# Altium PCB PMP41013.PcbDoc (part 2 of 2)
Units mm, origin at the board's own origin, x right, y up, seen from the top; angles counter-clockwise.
Board outline 51.82 x 50.04 mm, 2 copper layers (Top Layer, Bottom Layer), stack 0.325 mm thick; 134 components, 74 nets, 429 pads, 1513 vias.
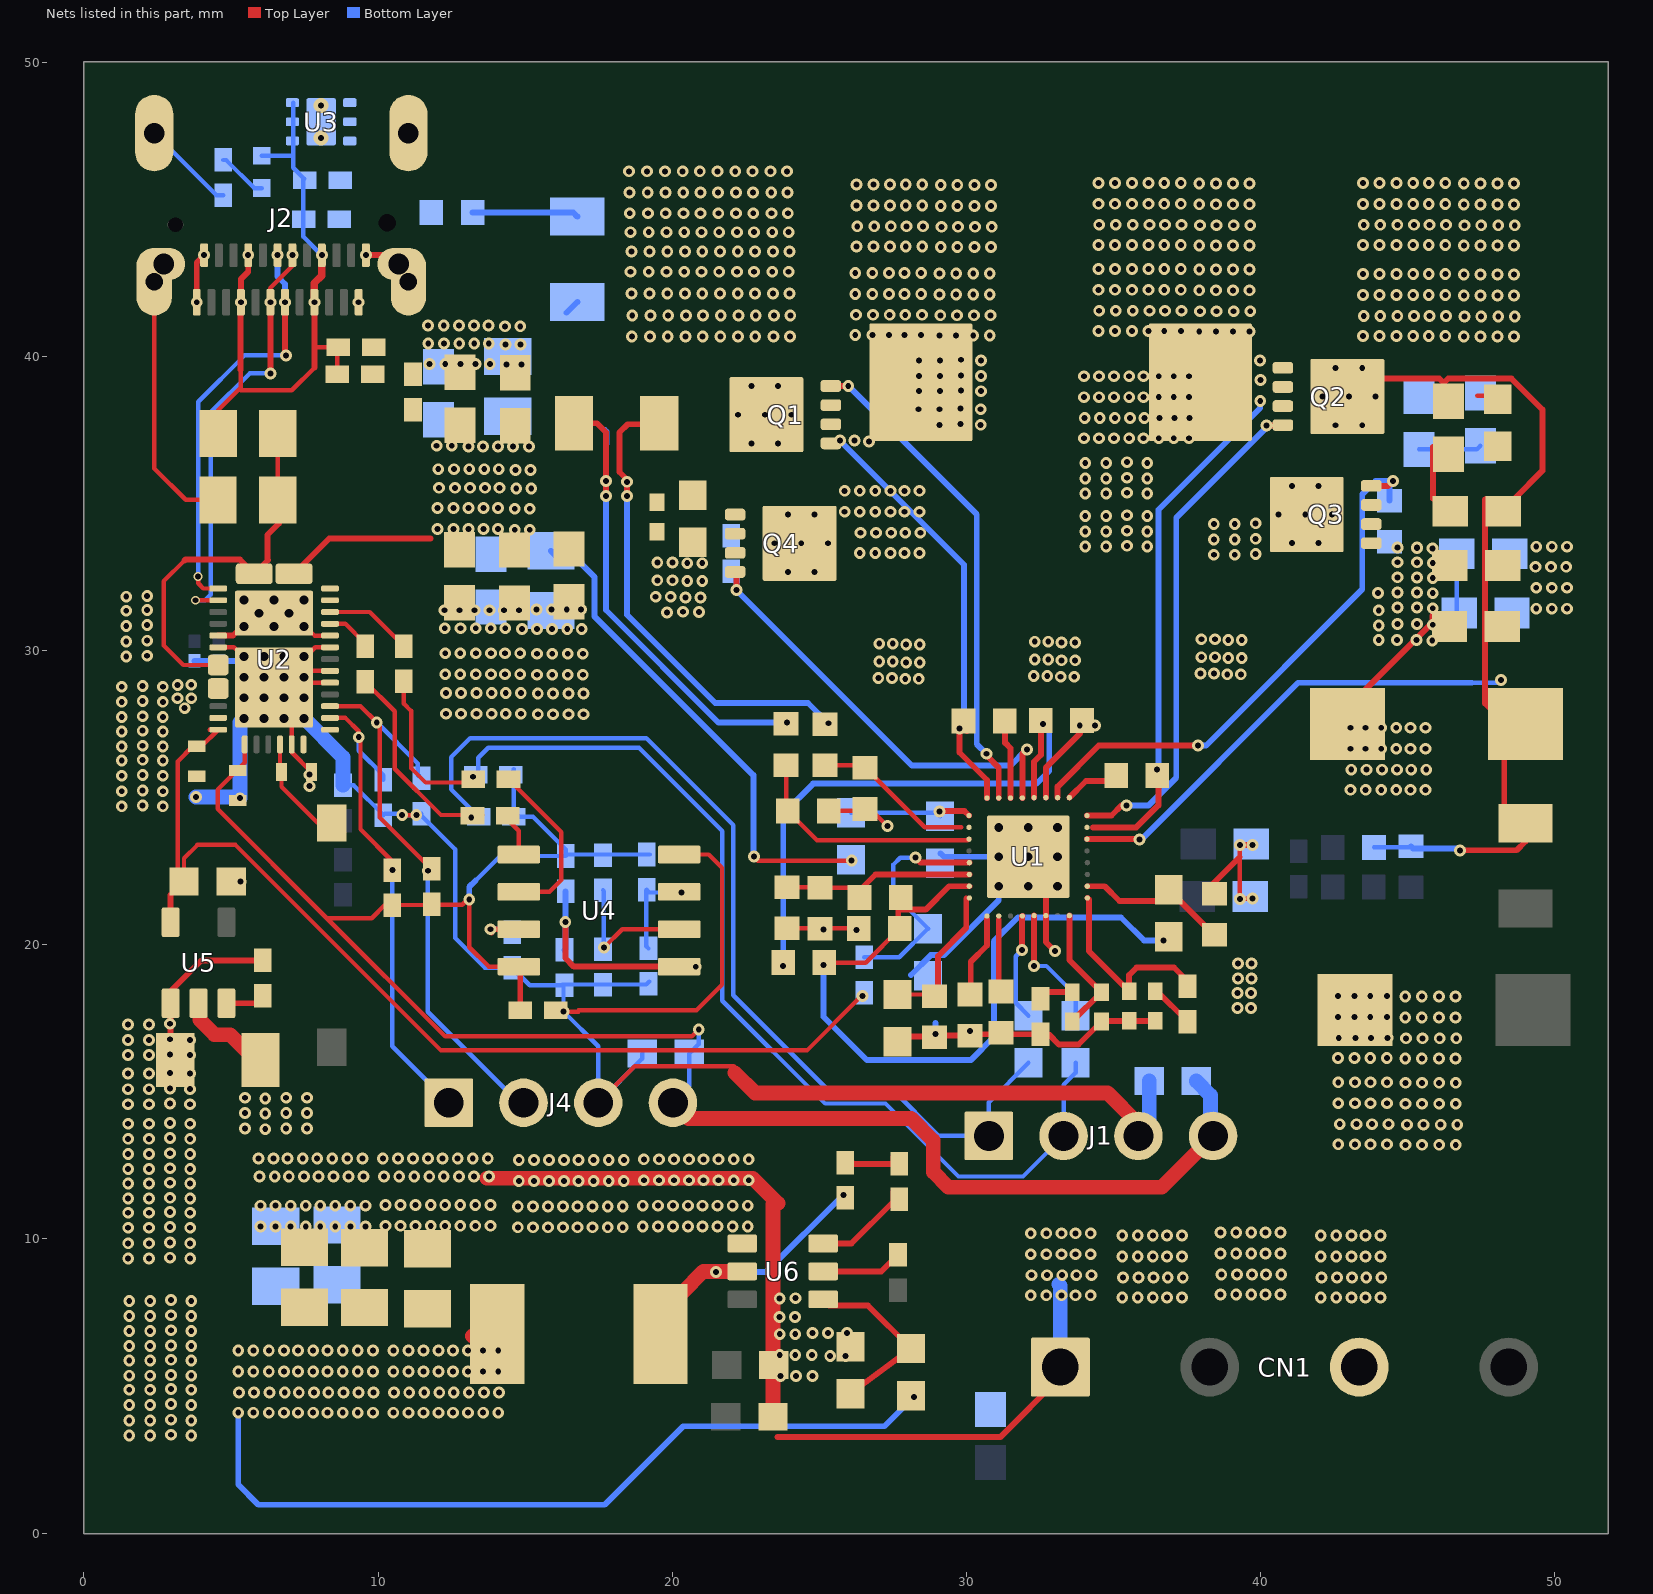
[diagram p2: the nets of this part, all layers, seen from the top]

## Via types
v1: diameter 0.4, hole 0.2, Top Layer to Bottom Layer, 1333 vias
v2: diameter 0.406, hole 0.203, Top Layer to Bottom Layer, tented both sides, 81 vias
v3: diameter 0.6, hole 0.3, Top Layer to Bottom Layer, 33 vias
v4: diameter 0.4, hole 0.2, Top Layer to Bottom Layer, tented both sides, 31 vias
v5: diameter 0.5, hole 0.2, Top Layer to Bottom Layer, 26 vias
v6: diameter 0.3, hole 0.2, Top Layer to Bottom Layer, tented both sides, 5 vias
v7: diameter 0.5, hole 0.2, Top Layer to Bottom Layer, tented both sides, 4 vias

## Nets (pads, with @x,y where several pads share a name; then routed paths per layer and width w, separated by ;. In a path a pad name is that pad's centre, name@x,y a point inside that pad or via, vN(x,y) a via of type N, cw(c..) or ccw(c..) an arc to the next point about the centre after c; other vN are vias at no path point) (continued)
GND: C1.2 C2.2 C3.2 C4.2 C5.2 C6.2 C7.2 C8.2 C9.2 C10.2 C11.2 C12.2 C13.2 C14.2 C15.2 C16.2 C17.2 C18.2 C19.2 C20.2 C21.2 C24.2 C25.1 C26.1 C27.2 C28.1 C29.2 C30.2 C33.2 C34.2 C35.1 C36.2 C37.2 C38.2 C39.2 C40.2 C41.2 C42.2 C43.1 C44.2 C45.2 C46.2 C47.2 C48.2 C49.1 C50.1 C51.2 C52.2 C53.2 C54.2 C55.2 C56.2 C57.2 C58.1 C59.2 C60.2 C61.2 C62.2 C64.2 C65.2 C66.2 C67.2 C68.2 CN1.1 J1.3 J2.A1 J2.A12 J2.B1 J2.B12 J2.S1 J2.S2 J2.S3 J2.S4 J4.3 Q3.1 Q3.2 Q3.3 Q4.1 Q4.2 Q4.3 R4.1 R16.2 R19.1 R20.1 R21.1 R22.2 R24.1 R32.1 R33.1 R42.1 R43.1 R44.1 R45.1 R50.1 U1.14 U1.27 U1.33 U2.5 U2.11 U2.12 U2.14 U2.31 U2.39 U3.1 U3.2 U3.3 U3.7@8.065,47.974 U4.4 U5.2 U6.1 | length 173.5
  Top Layer w0.15: J2.S2@2.394,42.54 2.394,36.189 3.461,35.122 C51.2@4.559,35.122 ; v4(3.816,25.019) 3.816,25.053 v4@3.839,25.075 ; U2.31@4.568,30.109 5.103,30.109 U2.39@6.468,28.744 ; C49.1@5.337,25.044 C49.1@5.349,25.057 ; U2.39@6.468,27.709 U2.39@6.468,28.744 ; U2.39@6.808,28.909 U2.39@6.664,28.909 ; U2.39@7.488,28.909 U2.11@8.368,28.909 ; C50.1@7.735,25.875 7.068,26.543 U2.5@7.068,26.809 7.068,28.144 U2.39@6.468,28.744 ; U2.12@8.368,29.309 U2.39@7.064,29.309 ; U2.14@8.368,30.109 7.864,30.109 U2.39@7.064,29.309 ; v4(10.82,24.409) v4(11.303,24.409) ; C57.2@16.035,17.776 16.082,17.729 v4(16.307,17.729) 16.815,17.729 ; 16.815,17.776 20.825,17.776 21.692,18.643 21.692,22.62 21.244,23.067 U4.4@20.237,23.067 ; J4.3@17.485,14.629 18.732,15.875 22.098,15.875 22.229,15.744 ; C40.2@23.911,20.557 26.328,20.557 C33.2@26.336,20.549 ; C29.2@25.327,24.549 26.494,24.549 C28.1@26.56,24.615 26.736,24.615 v2(27.311,24.04) ; v2(39.294,23.393) 39.294,22.981 v2(39.294,21.552) 39.306,21.565 v2(39.726,21.565) ; U2.39@6.468,28.744 U2.39@6.633,28.909 ; U2.39@6.633,28.909 7.033,29.309 U2.39@7.064,29.309 ; U2.39@6.633,28.909 U2.39@6.664,28.909 ; U2.39@6.664,28.909 U2.39@7.064,29.309
  Top Layer w0.2: v2(3.839,41.84) 3.839,43.19 v2(4.089,43.44) ; 3.937,17.45 U5.2@3.937,17.655 ; U5.2@3.994,17.918 U5.2@4.09,18.013 ; v2(9.589,43.44) 10.134,43.44 J2.S1@11.034,42.54 11.35,42.224 11.35,42.499 J2.S1@10.709,43.14 J2.S1@11.101,43.532 ; 23.581,3.264 31.15,3.264 33.194,5.308 CN1.1@33.194,5.643 ; R20.1@27.518,16.886 C42.2@28.645,16.886 ; C42.2@29.039,16.916 29.964,16.916 30.006,16.959 C37.2@32.522,16.959 32.796,16.959 33.145,16.61 33.814,16.61 C35.1@34.593,17.389 34.619,17.414 C39.2@35.533,17.414 C38.2@36.422,17.414 ; v3(32.101,22.99) 32.701,22.39 U1.14@32.701,20.99 32.701,20.094 v2(33.009,19.787) ; U1.27@32.701,25.001 32.701,26.021 33.856,27.176 C36.2@33.856,27.379 ; R21.1@38.584,21.806 38.352,22.039 39.294,22.981 ; v2(39.294,23.393) v2(39.726,23.393) ; C1.2@42.338,27.449 45.834,30.946 C13.2@45.834,31.197 ; C14.2@45.86,35.16 45.86,36.927
  Top Layer w0.5: U5.2@3.899,18.013 3.899,17.693 U5.2@3.937,17.655 ; 3.937,17.45 4.445,16.942 4.978,16.942 5.839,16.081 C59.2@6.007,16.081 ; v1@13.698,12.066 22.74,12.066 23.593,11.213 23.573,11.193 ; 22.131,15.645 22.816,14.961 34.798,14.961 35.845,13.914 J1.3@35.845,13.502 ; C61.2@23.427,3.956 23.427,11.181
  Bottom Layer w0.15: J2.S4@2.394,47.59 4.508,45.476 R4.1@4.738,45.476 ; 8.788,26.394 8.788,25.446 R24.1@8.812,25.423 9.17,25.423 R32.1@10.183,24.409 10.226,24.452 v4@10.82,24.452 ; v4(10.82,24.409) v4(11.303,24.409) 11.456,24.409 12.624,23.241 12.624,20.229 13.635,19.218 R42.1@14.56,19.218 15.156,18.622 16.231,18.622 16.257,18.648 R44.1@17.647,18.648 19.122,18.648 R45.1@19.223,18.75 ; R33.1@11.245,24.452 R33.1@11.48,24.452 ; R43.1@16.307,18.592 v4(16.307,17.729) 17.485,16.551 J4.3@17.485,14.629 18.986,16.13 C43.1@18.986,16.307 ; 36.212,14.376 36.212,14.453 ; C15.2@45.386,36.836 47.35,36.836 C12.2@47.471,36.957 ; C16.2@46.673,33.24 46.673,31.271 C19.2@46.698,31.246
  Bottom Layer w0.2: C52.2@3.762,29.651 5.304,29.651 v3(5.448,29.794) ; J2.S3@11.034,47.554 J2.S3@11.034,47.59 ; 28.115,18.972 28.789,19.646 29.236,19.646 31.101,21.51 v3(31.101,21.99) ; v2(28.956,16.967) 28.956,17.344 ; C27.2@29.127,23.1 29.236,22.99 v3(31.101,22.99)
  Bottom Layer w0.5: v4(3.816,25.019) 5.272,25.019 v4(5.309,24.983) 5.309,27.555 v3(5.448,27.694) ; v3(7.488,27.694) 8.788,26.394 8.812,26.37 R24.1@8.812,25.423 ; 33.136,8.463 33.194,8.405 CN1.1@33.194,5.643 ; J1.3@35.845,13.502 36.212,13.869 36.212,14.376 ; 36.212,14.453 C58.1@36.212,15.37
  other v1: 23.681,5.34 24.209,5.34 24.768,5.34 25.369,6.02 25.897,6.02 23.655,6.051 24.184,6.051 24.747,6.051 23.655,6.762 24.184,6.762 24.77,6.799 25.298,6.799 23.645,7.347 24.174,7.347 23.652,7.977 24.196,7.987 35.297,8.007 35.826,8.007 36.339,8.007 36.819,8.007 37.332,8.007 42.045,8.007 42.573,8.007 43.086,8.007 43.567,8.007 44.079,8.007 32.19,8.083 32.718,8.083 33.231,8.083 33.711,8.083 34.224,8.083 38.641,8.109 39.17,8.109 39.683,8.109 40.163,8.109 40.676,8.109 35.323,8.693 35.851,8.693 36.364,8.693 36.844,8.693 37.357,8.693 42.07,8.693 42.599,8.693 43.112,8.693 43.592,8.693 44.105,8.693 32.215,8.769 32.744,8.769 33.256,8.769 33.737,8.769 34.25,8.769 38.667,8.794 39.195,8.794 39.708,8.794 40.188,8.794 40.701,8.794 35.297,9.404 35.826,9.404 36.339,9.404 36.819,9.404 37.332,9.404 42.045,9.404 42.573,9.404 43.086,9.404 43.567,9.404 44.079,9.404 32.19,9.48 32.718,9.48 33.231,9.48 33.711,9.48 34.224,9.48 38.641,9.506 39.17,9.506 39.683,9.506 40.163,9.506 40.676,9.506 35.297,10.115 35.826,10.115 36.339,10.115 36.819,10.115 37.332,10.115 42.045,10.115 42.573,10.115 43.086,10.115 43.567,10.115 44.079,10.115 32.19,10.191 32.718,10.191 33.231,10.191 33.711,10.191 34.224,10.191 38.641,10.217 39.17,10.217 39.683,10.217 40.163,10.217 40.676,10.217 14.753,10.395 15.266,10.395 15.779,10.395 16.291,10.395 16.782,10.395 17.295,10.395 17.808,10.395 18.321,10.395 6.006,10.42 6.518,10.42 7.031,10.42 7.544,10.42 8.035,10.42 8.548,10.42 9.06,10.42 9.573,10.42 19.001,10.42 19.514,10.42 20.027,10.42 20.539,10.42 21.031,10.42 21.543,10.42 22.056,10.42 22.569,10.42 10.254,10.445 10.766,10.445 11.279,10.445 11.792,10.445 12.283,10.445 12.796,10.445 13.309,10.445 13.821,10.445 14.753,11.106 15.266,11.106 15.779,11.106 16.291,11.106 16.782,11.106 17.295,11.106 17.808,11.106 18.321,11.106 6.006,11.131 6.518,11.131 7.031,11.131 7.544,11.131 8.035,11.131 8.548,11.131 9.06,11.131 9.573,11.131 19.001,11.131 19.514,11.131 20.027,11.131 20.539,11.131 21.031,11.131 21.543,11.131 22.056,11.131 22.569,11.131 10.254,11.157 10.766,11.157 11.279,11.157 11.792,11.157 12.283,11.157 12.796,11.157 13.309,11.157 13.821,11.157 14.788,11.969 15.301,11.969 15.813,11.969 16.326,11.969 16.817,11.969 17.33,11.969 17.843,11.969 18.356,11.969 19.036,11.995 19.549,11.995 20.061,11.995 20.574,11.995 21.065,11.995 21.578,11.995 22.091,11.995 22.604,11.995 5.976,12.122 6.489,12.122 6.969,12.122 7.482,12.122 7.973,12.122 8.486,12.122 8.999,12.122 9.512,12.122 10.207,12.122 10.72,12.122 11.232,12.122 11.745,12.122 12.236,12.122 12.749,12.122 13.262,12.122 13.774,12.122 14.788,12.681 15.301,12.681 15.813,12.681 16.326,12.681 16.817,12.681 17.33,12.681 17.843,12.681 18.356,12.681 19.036,12.706 19.549,12.706 20.061,12.706 20.574,12.706 21.065,12.706 21.578,12.706 22.091,12.706 22.604,12.706 5.935,12.731 6.447,12.731 6.928,12.731 7.441,12.731 7.932,12.731 8.444,12.731 8.957,12.731 9.47,12.731 10.165,12.731 10.678,12.731 11.191,12.731 11.703,12.731 12.194,12.731 12.707,12.731 13.22,12.731 13.733,12.731 42.642,13.215 43.205,13.215 43.737,13.215 44.3,13.215 44.928,13.198 45.491,13.198 46.071,13.198 46.634,13.198 6.168,13.732 5.482,13.757 6.879,13.757 7.59,13.757 42.693,13.901 43.256,13.901 43.787,13.901 44.351,13.901 44.979,13.884 45.542,13.884 46.122,13.884 46.685,13.884 6.168,14.26 5.482,14.286 6.879,14.286 7.59,14.286 42.642,14.612 43.205,14.612 43.737,14.612 44.3,14.612 44.928,14.595 45.491,14.595 46.071,14.595 46.634,14.595 6.168,14.773 5.482,14.798 6.879,14.798 7.59,14.798 42.642,15.323 43.205,15.323 43.737,15.323 44.3,15.323 44.928,15.306 45.491,15.306 46.071,15.306 46.634,15.306 44.919,16.134 45.482,16.134 46.062,16.134 46.625,16.134 42.633,16.151 43.196,16.151 43.727,16.151 44.291,16.151 44.944,16.819 45.508,16.819 46.087,16.819 46.651,16.819 42.658,16.837 43.222,16.837 43.753,16.837 44.316,16.837 44.919,17.531 45.482,17.531 46.062,17.531 46.625,17.531 42.633,17.548 43.196,17.548 43.727,17.548 44.291,17.548 44.919,18.242 45.482,18.242 46.062,18.242 46.625,18.242 42.633,18.259 43.196,18.259 43.727,18.259 44.291,18.259 43.059,25.266 43.572,25.266 44.1,25.266 44.613,25.266 45.093,25.266 45.606,25.266 43.084,25.952 43.597,25.952 44.126,25.952 44.638,25.952 45.119,25.952 45.632,25.952 43.059,26.663 43.572,26.663 44.1,26.663 44.613,26.663 45.093,26.663 45.606,26.663 43.059,27.374 43.572,27.374 44.1,27.374 44.613,27.374 45.093,27.374 45.606,27.374 33.853,27.45 34.376,27.45 12.308,27.85 12.821,27.85 13.35,27.85 13.863,27.85 14.343,27.85 14.856,27.85 15.433,27.833 15.945,27.833 16.474,27.833 16.987,27.833 12.308,28.562 12.821,28.562 13.35,28.562 13.863,28.562 14.343,28.562 14.856,28.562 15.433,28.545 15.945,28.545 16.474,28.545 16.987,28.545 27.922,29.04 28.382,29.04 27.007,29.065 27.467,29.065 33.205,29.108 33.665,29.108 32.29,29.134 32.751,29.134 12.285,29.197 12.798,29.197 13.326,29.197 13.839,29.197 14.319,29.197 14.832,29.197 15.409,29.18 15.922,29.18 16.45,29.18 16.963,29.18 38.869,29.192 39.329,29.192 37.955,29.218 38.415,29.218 27.953,29.599 28.413,29.599 27.039,29.624 27.499,29.624 33.236,29.667 33.697,29.667 32.322,29.693 32.782,29.693 38.901,29.751 39.361,29.751 37.986,29.776 38.446,29.776 12.285,29.908 12.798,29.908 13.326,29.908 13.839,29.908 14.319,29.908 14.832,29.908 15.409,29.891 15.922,29.891 16.45,29.891 16.963,29.891 27.953,30.208 28.413,30.208 27.039,30.234 27.499,30.234 33.236,30.277 33.697,30.277 32.322,30.302 32.782,30.302 45.834,30.336 38.901,30.361 39.361,30.361 44.016,30.363 44.634,30.362 45.3,30.358 37.986,30.386 38.446,30.386 14.893,30.734 15.406,30.734 15.919,30.734 16.431,30.734 16.923,30.734 12.27,30.759 12.809,30.759 13.321,30.759 13.834,30.759 14.325,30.759 44.016,30.854 45.851,30.879 44.651,30.904 45.317,30.9 19.819,31.295 20.365,31.321 12.254,31.369 12.767,31.369 13.28,31.369 13.792,31.369 14.284,31.369 14.796,31.369 44.016,31.367 15.39,31.394 15.903,31.394 16.416,31.394 16.907,31.394 45.851,31.439 44.651,31.464 45.317,31.46 20.454,31.803 20.965,31.803 19.438,31.829 19.949,31.829 43.99,31.961 45.851,31.951 44.651,31.977 45.317,31.973 20.511,32.362 21.022,32.362 19.495,32.387 20.006,32.387 45.851,32.464 44.651,32.49 45.317,32.485 20.511,32.972 21.022,32.972 45.851,32.977 19.495,32.997 20.006,32.997 44.651,33.002 45.317,32.998 45.317,33.489 45.851,33.468 44.651,33.493 14.37,39.718 14.883,39.718 11.747,39.743 12.285,39.743 12.798,39.743 13.311,39.743 13.802,39.743 14.332,40.408 14.845,40.408 11.709,40.433 12.248,40.433 12.76,40.433 13.273,40.433 13.764,40.433 14.321,41.021 14.834,41.021 11.699,41.046 12.237,41.046 12.75,41.046 13.262,41.046 13.753,41.046
  other v2: 25.946,6.807 30.123,17.069 39.221,17.854 39.678,17.856 39.221,18.364 39.678,18.364 39.232,18.852 39.689,18.855 39.232,19.363 39.689,19.363 26.264,20.507 25.146,20.523 20.905,31.312 45.851,33.477 44.651,33.503 45.317,33.498 9.339,41.84
  other v3: 32.101,21.99 33.101,21.99 33.101,22.99 31.101,23.99 32.101,23.99 33.101,23.99 6.128,27.694 6.808,27.694 5.448,28.394 6.128,28.394 6.808,28.394 7.488,28.394 5.448,29.094 6.128,29.094 6.808,29.094 7.488,29.094 6.128,29.794 6.808,29.794 7.488,29.794
  other v4: 5.33,22.144 7.671,25.39 7.671,25.781
  other v5: 8.065,47.424 8.065,48.524
I2C_SCL: J1.2 R15.1 R25.2 R28.2 R39.1 | length 38.7
  Top Layer w0.15: R25.2@10.881,28.949 10.881,28.194 11.125,27.949 11.125,26.006 11.616,25.515 13.435,25.515 R39.1@13.487,25.567
  Bottom Layer w0.15: R28.2@13.411,25.975 13.411,26.357 13.749,26.695 18.872,26.695 21.703,23.865 21.703,18.099 25.197,14.605 27.25,14.605 29.733,12.122 31.925,12.122 J1.2@33.305,13.502 33.305,15.239 33.712,15.646 R15.1@33.712,15.988
  other v4: 13.236,25.712
I2C_SDA: J1.1 R17.1 R27.2 R29.2 R41.1 | length 40
  Top Layer w0.15: R27.2@9.561,28.943 10.566,27.937 10.566,25.984 12.14,24.41 R41.1@13.537,24.41
  Bottom Layer w0.15: R29.2@13.419,24.349 12.484,25.284 12.484,26.375 13.134,27.026 19.116,27.026 22.073,24.069 22.073,18.288 25.273,15.088 27.479,15.088 29.065,13.502 J1.1@30.765,13.502 30.765,14.641 R17.1@32.112,15.988
  other v4: 13.17,24.329
I2CS_SCL: J4.2 R31.1 R33.2 U2.9 | length 19.4
  Top Layer w0.15: U2.9@8.368,28.109 9.406,28.109 v4(9.956,27.559) 10.058,27.457 10.058,24.326 11.603,22.781 R31.1@11.603,22.562
  Bottom Layer w0.15: v4(9.956,27.559) 11.354,26.162 11.354,25.778 R33.2@11.48,25.652 ; v4(11.693,22.517) 11.693,17.72 14.785,14.629 J4.2@14.945,14.629
I2CS_SDA: J4.1 R30.1 R32.2 U2.8 | length 16.9
  Top Layer w0.15: U2.8@8.368,27.709 8.892,27.709 9.347,27.254 v4(9.347,27.056) 9.406,26.998 9.406,23.924 10.488,22.842 v4(10.488,22.539)
  Bottom Layer w0.15: v4(9.347,27.056) 9.347,26.594 10.183,25.758 R32.2@10.183,25.609 ; v4(10.488,22.539) 10.488,16.546 J4.1@12.405,14.629
ILIM_HIZ: C40.1 R11.2 R16.1 U1.6 | length 6.6
  Top Layer w0.15: C40.1@23.911,21.957 25.005,21.957 R16.1@25.018,21.943 26.029,21.943 R11.2@26.367,21.604
  Top Layer w0.2: R11.2@26.316,21.793 26.914,22.39 U1.6@30.101,22.39
LDO_1V5: C50.2 S1.2 U2.4 | length 3.3
  Top Layer w0.15: U2.4@6.668,26.809 6.668,25.927 C50.2@6.719,25.875 6.719,25.371 7.927,24.163 S1.2@8.02,24.163
LDO_3V3: C43.2 C49.2 C57.1 C58.2 J1.4 J4.4 R28.1 R29.1 R30.2 R31.2 R34.2 R35.2 R36.2 U2.1 U4.8 | length 69.4
  Top Layer w0.15: U2.1@5.468,26.809 5.468,26.191 4.547,25.27 4.547,24.62 8.262,20.904 ; U4.8@14.325,19.257 13.763,19.257 13.103,19.917 v4(13.103,21.539) 13.042,21.539 12.865,21.362 11.603,21.362 11.591,21.351 10.234,21.351 9.787,20.904 8.262,20.904 ; v4(20.904,17.12) 20.67,16.886 12.281,16.886 8.262,20.904
  Top Layer w0.2: U4.8@14.325,19.257 U4.8@14.787,19.257 14.835,19.21 C57.1@14.835,17.776
  Top Layer w0.5: J4.4@20.025,14.629 20.557,14.097 28.118,14.097 28.871,13.344 28.871,12.277 29.388,11.76 36.644,11.76 J1.4@38.385,13.502
  Bottom Layer w0.15: 13.321,22.186 14.152,23.016 R34.2@16.378,23.016 ; R28.1@14.611,25.975 14.611,24.357 R29.1@14.619,24.349 15.267,24.349 16.378,23.237 R34.2@16.378,23.016 ; R36.2@19.239,23.068 R36.2@19.137,23.068 16.43,23.068 R34.2@16.378,23.016 ; J4.4@20.025,14.629 20.586,15.19 C43.2@20.586,16.307 20.904,16.625 v4(20.904,17.12)
  Bottom Layer w0.2: v4(13.103,21.539) 13.103,21.967 13.321,22.186
  Bottom Layer w0.5: C58.2@37.812,15.37 38.295,14.887 38.295,13.591 J1.4@38.385,13.502
NetC1_1: C1.1 C4.1 C12.1 C13.1 C14.1 C15.1 C16.1 C17.1 C18.1 C19.1 C32.1 Q2.5 Q2.6 Q2.7 Q2.8 Q2.9 R2.1 R8.1 U1.22 | length 46.2
  Top Layer w0.15: 47.371,38.657 48.089,38.657 C4.1@48.215,38.531
  Top Layer w0.2: U1.22@34.101,23.59 35.87,23.59 v2(35.89,23.57) ; Q2.9@43.468,38.56 44.155,39.247 46.072,39.247 46.226,39.093 46.38,39.247 48.525,39.247 49.579,38.193 49.579,36.11 48.628,35.16 47.66,35.16 47.634,35.134 47.634,28.202 48.388,27.449 48.284,27.345 R2.1@48.284,23.895 ; v2(46.778,23.211) 48.704,23.211 49.006,23.513 R2.1@49.006,24.133
  Bottom Layer w0.15: R8.1@43.856,23.309 45.073,23.309 C32.1@45.112,23.348 ; 47.193,28.905 48.04,28.905 v2@48.184,29.049
  Bottom Layer w0.2: v2(35.89,23.57) 35.94,23.57 41.275,28.905 47.193,28.905 ; C32.1@45.112,23.348 45.184,23.276 46.713,23.276 v2(46.778,23.211)
  other v1: 49.372,31.424 49.901,31.424 50.413,31.424 49.372,32.136 49.901,32.136 50.413,32.136 49.347,32.847 49.875,32.847 50.388,32.847 49.372,33.533 49.901,33.533 50.413,33.533 46.909,40.673 47.472,40.673 48.052,40.673 48.615,40.673 43.48,40.69 44.043,40.69 44.623,40.69 45.186,40.69 45.718,40.69 46.281,40.69 46.934,41.359 47.498,41.359 48.077,41.359 48.641,41.359 43.505,41.376 44.069,41.376 44.648,41.376 45.212,41.376 45.743,41.376 46.307,41.376 46.909,42.07 47.472,42.07 48.052,42.07 48.615,42.07 43.48,42.087 44.043,42.087 44.623,42.087 45.186,42.087 45.718,42.087 46.281,42.087 46.909,42.781 47.472,42.781 48.052,42.781 48.615,42.781 43.48,42.798 44.043,42.798 44.623,42.798 45.186,42.798 45.718,42.798 46.281,42.798 46.909,43.768 47.472,43.768 48.052,43.768 48.615,43.768 43.48,43.785 44.043,43.785 44.623,43.785 45.186,43.785 45.718,43.785 46.281,43.785 46.934,44.454 47.498,44.454 48.077,44.454 48.641,44.454 43.505,44.471 44.069,44.471 44.648,44.471 45.212,44.471 45.743,44.471 46.307,44.471 46.909,45.165 47.472,45.165 48.052,45.165 48.615,45.165 43.48,45.182 44.043,45.182 44.623,45.182 45.186,45.182 45.718,45.182 46.281,45.182 46.909,45.876 47.472,45.876 48.052,45.876 48.615,45.876 43.48,45.893 44.043,45.893 44.623,45.893 45.186,45.893 45.718,45.893 46.281,45.893
  other v2: 48.166,29.007
  other v5: 42.552,37.661 43.457,37.661 42.1,38.636 43.005,38.636 42.552,39.61 43.457,39.61
  other v7: 43.91,38.636
NetC3_1: C3.1 C21.1 Q1.5 Q1.6 Q1.7 Q1.8 Q1.9 R1.2 R6.2 | length 16
  Top Layer w0.2: v2(18.466,35.255) v2(18.466,35.738) 18.466,35.814 18.212,36.068 18.212,37.417 18.487,37.692 18.898,37.692
  Bottom Layer w0.2: v2(18.466,35.738) v2(18.466,35.255) 18.466,31.217 21.463,28.219 24.617,28.219 v2(25.307,27.529)
  other v1: 18.628,40.675 19.243,40.675 19.848,40.675 20.451,40.675 21.035,40.675 21.637,40.675 22.241,40.675 22.825,40.675 23.442,40.675 24,40.675 18.644,41.389 19.258,41.389 19.863,41.389 20.467,41.389 21.051,41.389 21.652,41.389 22.256,41.389 22.84,41.389 23.457,41.389 24.015,41.389 18.615,42.139 19.23,42.139 19.835,42.139 20.438,42.139 21.022,42.139 21.624,42.139 22.228,42.139 22.812,42.139 23.428,42.139 23.987,42.139 18.587,42.875 19.202,42.875 19.806,42.875 20.41,42.875 20.994,42.875 21.596,42.875 22.2,42.875 22.784,42.875 23.4,42.875 23.959,42.875 18.615,43.563 19.23,43.563 19.835,43.563 20.438,43.563 21.022,43.563 21.624,43.563 22.228,43.563 22.812,43.563 23.428,43.563 23.987,43.563 18.587,44.221 19.202,44.221 19.806,44.221 20.41,44.221 20.994,44.221 21.596,44.221 22.2,44.221 22.784,44.221 23.4,44.221 23.959,44.221 18.559,44.866 19.174,44.866 19.778,44.866 20.382,44.866 20.966,44.866 21.568,44.866 22.172,44.866 22.756,44.866 23.372,44.866 23.931,44.866 18.552,45.568 19.167,45.568 19.771,45.568 20.375,45.568 20.959,45.568 21.561,45.568 22.165,45.568 22.749,45.568 23.365,45.568 23.924,45.568 18.532,46.29 19.147,46.29 19.752,46.29 20.355,46.29 20.939,46.29 21.541,46.29 22.145,46.29 22.729,46.29 23.346,46.29 23.904,46.29
  other v5: 22.696,37.042 23.601,37.042 23.148,38.017 24.053,38.017 22.696,38.992 23.601,38.992
  other v7: 22.243,38.017
NetC22_1: C22.1 U1.30 | length 2.4
  Top Layer w0.2: C22.1@31.38,27.298 31.318,27.236 31.318,26.861 31.501,26.678 U1.30@31.501,24.99
NetC22_2: C22.2 L1.1 Q1.1 Q1.2 Q1.3 Q4.5 Q4.6 Q4.7 Q4.8 Q4.9 U1.32 | length 14.4
  Top Layer w0.2: v2(29.769,27.356) C22.2@29.769,27.249 ; C22.2@29.789,27.229 C22.2@29.769,27.249 ; C22.2@29.98,27.298 C22.2@30.021,27.257 ; U1.32@30.701,24.99 30.701,25.602 29.769,26.534 C22.2@29.769,27.249
  Bottom Layer w0.2: v2(25.705,37.135) 29.921,32.918 29.921,27.508 v2(29.769,27.356)
  other v1: 26.376,33.32 26.904,33.32 27.417,33.32 27.897,33.32 28.41,33.32 26.401,34.006 26.93,34.006 27.442,34.006 27.923,34.006 28.436,34.006 25.863,34.717 26.376,34.717 26.904,34.717 27.417,34.717 27.897,34.717 28.41,34.717 25.863,35.428 26.376,35.428 26.904,35.428 27.417,35.428 27.897,35.428 28.41,35.428 29.088,37.672 30.485,37.672 29.799,37.698 28.376,38.201 29.088,38.201 30.485,38.201 29.799,38.226 28.392,38.817 29.103,38.817 30.5,38.817 29.814,38.842 28.392,39.33 29.103,39.33 30.5,39.33 29.814,39.355 28.392,39.858 29.103,39.858 30.5,39.858 29.814,39.884 26.224,40.726 26.804,40.726 27.367,40.726 27.898,40.726 28.462,40.726 29.09,40.709 29.653,40.709 30.233,40.709 30.796,40.709 26.25,41.412 26.829,41.412 27.393,41.412 27.924,41.412 28.487,41.412 29.115,41.395 29.679,41.395 30.258,41.395 30.822,41.395 26.224,42.123 26.804,42.123 27.367,42.123 27.898,42.123 28.462,42.123 29.09,42.106 29.653,42.106 30.233,42.106 30.796,42.106 26.224,42.834 26.804,42.834 27.367,42.834 27.898,42.834 28.462,42.834 29.09,42.817 29.653,42.817 30.233,42.817 30.796,42.817 29.129,43.717 29.692,43.717 30.272,43.717 30.835,43.717 26.263,43.734 26.843,43.734 27.406,43.734 27.938,43.734 28.501,43.734 29.154,44.403 29.718,44.403 30.297,44.403 30.861,44.403 26.289,44.42 26.868,44.42 27.432,44.42 27.963,44.42 28.527,44.42 29.129,45.114 29.692,45.114 30.272,45.114 30.835,45.114 26.263,45.131 26.843,45.131 27.406,45.131 27.938,45.131 28.501,45.131 29.129,45.825 29.692,45.825 30.272,45.825 30.835,45.825 26.263,45.842 26.843,45.842 27.406,45.842 27.938,45.842 28.501,45.842
  other v2: 26.685,37.113 26.198,37.136
  other v5: 23.933,32.672 24.838,32.672 23.48,33.647 24.385,33.647 23.933,34.622 24.838,34.622
  other v7: 25.29,33.647
NetC23_1: C23.1 U1.25 | length 2.1
  Top Layer w0.2: U1.25@33.501,25.001 34.068,25.567 C23.1@35.342,25.567
NetC23_2: C23.2 L1.2 Q2.1 Q2.2 Q2.3 Q3.5 Q3.6 Q3.7 Q3.8 Q3.9 U1.23 | length 17.5
  Top Layer w0.2: 34.301,23.99 35.776,23.99 36.525,24.74 36.525,25.351 C23.2@36.742,25.567
  Bottom Layer w0.2: v2(36.474,25.959) 36.53,26.014 36.53,34.788 39.989,38.247 v2(39.989,38.481) ; 41.137,35.154 41.209,35.081
  other v1: 38.411,33.259 39.122,33.259 39.833,33.284 34.041,33.534 34.752,33.534 36.149,33.534 35.463,33.559 38.411,33.772 39.122,33.772 39.833,33.797 34.041,34.046 34.752,34.046 36.149,34.046 35.463,34.072 38.411,34.3 39.122,34.3 39.833,34.326 34.041,34.575 34.752,34.575 36.149,34.575 35.463,34.6 34.041,35.337 34.752,35.337 36.149,35.337 35.463,35.362 34.041,35.85 34.752,35.85 36.149,35.85 35.463,35.875 34.041,36.378 34.752,36.378 36.149,36.378 35.463,36.404 33.995,37.217 34.508,37.217 35.021,37.217 35.533,37.217 36.025,37.217 36.537,37.217 37.05,37.217 37.563,37.217 34.021,37.903 34.533,37.903 35.046,37.903 35.559,37.903 36.05,37.903 36.563,37.903 37.075,37.903 37.588,37.903 33.995,38.614 34.508,38.614 35.021,38.614 35.533,38.614 36.025,38.614 36.537,38.614 37.05,38.614 37.563,38.614 33.995,39.325 34.508,39.325 35.021,39.325 35.533,39.325 36.025,39.325 36.537,39.325 37.05,39.325 37.563,39.325 37.917,40.847 38.481,40.847 39.06,40.847 39.624,40.847 34.488,40.864 35.052,40.864 35.631,40.864 36.195,40.864 36.726,40.864 37.29,40.864 37.943,41.533 38.506,41.533 39.086,41.533 39.649,41.533 34.514,41.55 35.077,41.55 35.657,41.55 36.22,41.55 36.751,41.55 37.315,41.55 37.917,42.244 38.481,42.244 39.06,42.244 39.624,42.244 34.488,42.261 35.052,42.261 35.631,42.261 36.195,42.261 36.726,42.261 37.29,42.261 37.917,42.955 38.481,42.955 39.06,42.955 39.624,42.955 34.488,42.972 35.052,42.972 35.631,42.972 36.195,42.972 36.726,42.972 37.29,42.972 37.917,43.772 38.481,43.772 39.06,43.772 39.624,43.772 34.488,43.789 35.052,43.789 35.631,43.789 36.195,43.789 36.726,43.789 37.29,43.789 37.943,44.457 38.506,44.457 39.086,44.457 39.649,44.457 34.514,44.475 35.077,44.475 35.657,44.475 36.22,44.475 36.751,44.475 37.315,44.475 37.917,45.169 38.481,45.169 39.06,45.169 39.624,45.169 34.488,45.186 35.052,45.186 35.631,45.186 36.195,45.186 36.726,45.186 37.29,45.186 37.917,45.88 38.481,45.88 39.06,45.88 39.624,45.88 34.488,45.897 35.052,45.897 35.631,45.897 36.195,45.897 36.726,45.897 37.29,45.897
  other v2: 40.005,39.192 39.98,39.853
  other v5: 41.064,33.65 41.969,33.65 41.517,34.625 42.422,34.625 41.064,35.6 41.969,35.6
  other v7: 40.612,34.625
NetC24_1: C24.1 R3.1 | length 3.6
  Bottom Layer w0.2: C24.1@13.215,44.891 16.636,44.891 R3.1@16.776,44.751
NetC25_2: C25.2 Q4.4 U1.29 | length 15.7
  Top Layer w0.2: v2(22.184,32.055) Q4.4@22.184,32.759 ; U1.29@31.901,24.99 31.901,26.491 v2(32.055,26.645)
  Bottom Layer w0.2: C25.2@22.01,32.702 22.184,32.528 v2(22.184,32.055) 28.15,26.089 31.499,26.089 v2(32.055,26.645)
NetC26_2: C26.2 Q3.4 U1.26 | length 19.5
  Top Layer w0.2: U1.26@33.101,25.001 33.101,25.373 34.499,26.772 v2(37.871,26.772) ; Q3.4@43.764,35.6 44.338,35.6 v2(44.501,35.763)
  Bottom Layer w0.2: v2(37.871,26.772) 38.148,26.772 43.456,32.079 43.456,35.315 43.904,35.763 v2(44.501,35.763) 44.437,35.7 44.388,35.7 C26.2@44.388,35.1
NetC27_1: C27.1 R5.2 U1.1 | length 4.2
  Top Layer w0.2: v2(29.083,24.536) 29.096,24.549 29.932,24.549 U1.1@30.091,24.39
  Bottom Layer w0.15: R5.2@26.079,24.493 28.984,24.493 C27.1@29.107,24.37
NetC28_2: C28.2 R6.1 U1.2 | length 5.9
  Top Layer w0.15: R6.1@25.187,26.096 26.479,26.096 C28.2@26.56,26.015 28.584,23.99 29.82,23.99
  Top Layer w0.2: R6.1@25.187,26.096 R6.1@25.477,25.806
NetC29_1: C29.1 R7.1 U1.3 | length 7.8
  Top Layer w0.15: R7.1@23.872,26.106 23.872,24.877 C29.1@23.874,24.876 ; C29.1@23.927,24.549 24.923,23.552 30.052,23.552 U1.3@30.091,23.59
NetC35_2: C35.2 R12.2 U1.16 | length 4.5
  Top Layer w0.2: U1.16@33.501,20.99 33.501,19.481 C35.2@34.593,18.389 33.603,17.398 R12.2@33.603,17.389
NetC37_1: C37.1 R12.1 | length 1.2
  Top Layer w0.2: C37.1@32.522,18.159 32.752,18.389 R12.1@33.603,18.389
NetC38_1: C38.1 R13.2 | length 1.5
  Top Layer w0.2: C38.1@36.422,18.414 36.49,18.414 R13.2@37.514,17.39
NetC39_1: C39.1 R13.1 U1.17 | length 6.8
  Top Layer w0.2: U1.17@34.112,21.59 34.161,21.54 34.161,19.786 C39.1@35.533,18.414 35.533,18.973 35.786,19.226 37.056,19.226 37.514,18.768 R13.1@37.514,18.59
NetC41_1: C41.1 U1.9 | length 3.1
  Top Layer w0.15: C41.1@29.868,18.564 C41.1@30.117,18.315
  Top Layer w0.2: C41.1@30.123,18.309 30.15,18.336 30.15,19.426 30.701,19.978 30.701,20.866
NetC42_1: C42.1 R20.2 U1.8 | length 4.7
  Top Layer w0.15: R20.2@27.657,18.308 28.747,18.308 28.856,18.308 C42.1@28.912,18.252
  Top Layer w0.2: C42.1@28.687,18.248 C42.1@28.747,18.308 ; C42.1@29.039,18.6 29.039,19.621 29.996,20.577 29.996,21.572
NetC45_1: C45.1 C46.1 C47.1 C48.1 D1.1 J2.A4 J2.A9 J2.B4 J2.B9 L2.1 U3.4 U3.5 U3.6 | length 21.6
  Top Layer w0.15: L2.1@4.565,37.38 4.565,38.173 5.33,38.938 ; 5.33,39.544 5.33,38.938 ; 7.839,39.616 7.073,38.849 5.33,38.849 5.33,38.938 ; 7.839,40.335 7.862,40.313 C48.1@8.653,40.313 8.62,40.279 C47.1@8.62,39.388
  Top Layer w0.2: 5.33,39.544 5.33,41.581 5.339,41.59 v2(5.339,41.84) ; J2.A9@5.339,42.09 5.339,42.627 5.589,42.877 v2(5.589,43.44) ; 7.839,39.616 7.839,40.335 v2(7.839,41.84) J2.A4@7.886,41.793
  Top Layer w0.254: v2(7.839,41.84) 7.839,42.494 8.089,42.744 v2(8.089,43.44)
  Bottom Layer w0.15: D1.1@6.046,46.821 7.107,46.821 7.116,46.812 ; U3.6@7.116,48.616 7.116,47.974 7.116,46.812 ; v2(8.089,43.44) 7.457,44.072 7.457,46.009 7.486,46.038 7.116,46.409 7.116,46.812
NetC63_1: C63.1 R47.2 | length 2
  Top Layer w0.2: C63.1@25.887,12.824 26.158,12.554 27.52,12.554 R47.2@27.52,12.808
NetC63_2: C63.2 L3.1 U6.2 | length 8.4
  Top Layer w0.5: L3.1@19.747,8.174 20.34,8.174 21.062,8.895 U6.2@22.381,8.895
  Bottom Layer w0.2: v2(21.484,8.88) 23.195,8.88 25.811,11.496 v2(25.828,11.496)
NetD1_2: D1.2 R4.2 | length 1.7
  Bottom Layer w0.15: R4.2@4.738,46.676 4.836,46.676 5.79,45.721 D1.2@6.046,45.721
NetQ1_4: Q1.4 U1.31 | length 16.8
  Top Layer w0.2: Q1.4@25.293,38.992 25.977,38.992 v2(25.984,39) ; v2(30.681,26.492) 30.681,26.439 31.101,26.019 U1.31@31.101,24.99
  Bottom Layer w0.2: v2(25.984,39) 30.353,34.631 30.353,26.82 v2(30.681,26.492)
NetQ2_4: Q2.4 U1.24 | length 17.4
  Top Layer w0.2: U1.24@34.101,24.39 34.931,24.39 35.28,24.74 v2(35.441,24.74) ; v2(40.194,37.655) 40.75,37.655 Q2.4@40.757,37.661
  Bottom Layer w0.2: v2(35.441,24.74) 36.195,24.74 37.135,25.679 37.135,34.519 40.194,37.578 v2(40.194,37.655)
NetR14_1: R14.1 R21.2 U1.18 | length 6.1
  Top Layer w0.2: U1.18@34.112,21.99 34.698,21.99 35.202,21.486 36.523,21.486 36.752,21.716 R14.1@36.752,22.096 ; R14.1@36.637,21.98 R14.1@36.752,22.096 ; R14.1@36.854,22.197 R14.1@36.752,22.096 ; R14.1@36.879,22.071 36.879,21.87 38.343,20.406 R21.2@38.584,20.406
NetR15_2: R15.2 U1.13 | length 4.1
  Top Layer w0.2: v2(32.301,19.279) 32.301,20.979 32.307,20.985 U1.13@32.301,20.99
  Bottom Layer w0.15: v2(32.301,19.279) 32.722,19.279 33.712,18.288 R15.2@33.712,17.678
NetR17_2: R17.2 U1.12 | length 3.7
  Top Layer w0.2: v2(31.891,19.827) 31.891,20.97 U1.12@31.901,20.98
  Bottom Layer w0.15: v2(31.891,19.827) 31.674,19.61 31.674,18.026 R17.2@32.112,17.588
NetR18_2: R18.2 R19.2 U1.5 | length 8
  Top Layer w0.2: v2(28.27,22.962) 28.441,22.79 U1.5@30.101,22.79
  Bottom Layer w0.15: R18.2@26.531,19.571 27.72,19.571 R19.2@28.699,20.549 27.519,21.729 27.519,22.728 27.753,22.962 v2(28.27,22.962)
NetR22_1: R22.1 U1.10 | length 2.5
  Top Layer w0.2: 31.101,20.853 31.101,18.481 R22.1@31.171,18.411
NetR25_1: R25.1 U2.17 | length 3
  Top Layer w0.15: U2.17@8.368,31.309 9.721,31.309 R25.1@10.881,30.149
NetR27_1: R27.1 U2.16 | length 1.6
  Top Layer w0.15: U2.16@8.368,30.909 8.892,30.909 9.561,30.241 R27.1@9.561,30.143
NetR34_1: R34.1 R43.2 U4.1 | length 7.8
  Top Layer w0.15: U4.1@20.237,19.257 20.242,19.253 v4(20.803,19.253)
  Top Layer w0.2: v4(16.368,20.775) 16.368,19.547 16.657,19.257 U4.1@20.237,19.257
  Bottom Layer w0.2: R43.2@16.338,19.822 16.378,19.863 R34.1@16.378,21.816
NetR35_1: R35.1 R44.2 U4.2 | length 4.8
  Top Layer w0.15: v4(17.678,19.906) 18.3,20.527 U4.2@20.237,20.527
  Bottom Layer w0.15: R35.1@17.647,21.849 17.678,21.817 v4(17.678,19.906)
NetR36_1: R36.1 R45.2 U4.3 | length 3.2
  Bottom Layer w0.15: R36.1@19.137,21.868 19.122,21.852 19.122,19.945 R45.2@19.193,19.874 ; R36.1@19.193,21.812 19.228,21.777 v4(20.314,21.777)
NetR39_2: R39.2 U4.6 | length 5.8
  Top Layer w0.15: R39.2@14.436,25.626 16.231,23.831 16.231,22.2 15.828,21.797 U4.6@14.787,21.797
NetR41_2: R41.2 U4.5 | length 1.5
  Top Layer w0.15: R41.2@14.413,24.383 14.413,24.25 14.787,23.875 U4.5@14.787,23.067
NetR42_2: R42.2 U4.7 | length 2
  Top Layer w0.2: v4@13.858,20.422 13.821,20.458 v4(13.821,20.527) 14.576,20.527 14.682,20.422 U4.7@14.787,20.527
  Bottom Layer w0.2: v4(13.821,20.527) 14.451,20.527 R42.2@14.56,20.418
NetR46_1: R46.1 U5.3 | length 1.3
  Top Layer w0.2: U5.3@4.849,18.013 5.828,18.013 R46.1@6.086,18.271
NetR47_1: R47.1 U6.6 | length 3.3
  Top Layer w0.2: U6.6@25.131,9.845 26.091,9.845 27.52,11.274 R47.1@27.52,11.608
NetR48_1: R48.1 U6.5 | length 2.8
  Top Layer w0.2: U6.5@25.131,8.895 27.108,8.895 R48.1@27.677,9.464
NetR49_1: R49.1 R50.2 U6.4 | length 6.2
  Top Layer w0.2: U6.4@25.131,7.945 25.338,7.738 26.652,7.738 R49.1@28.115,6.275 27.48,5.801 26.691,5.212 R50.2@26.056,4.738
NetU2_15: U2.15 U2.30 U2.40 | length 4.4
  Top Layer w0.15: U2.40@6.468,31.269 v3(6.978,31.269) 7.085,31.269 7.855,30.499 8.357,30.499 U2.15@8.368,30.509
  Top Layer w0.2: U2.30@4.568,30.509 5.072,30.509 5.832,31.269 v3(5.958,31.269) U2.40@6.468,31.269
  other v3: 5.448,30.819 6.468,30.819 7.488,30.819 5.448,31.719 6.468,31.719 7.488,31.719
NTC: CN1.3
P3V3: C44.1 C60.1 R18.1 U2.38 U5.5 | length 35.1
  Top Layer w0.15: C60.1@3.19,22.477 3.19,26.228 3.707,26.745 C44.1@3.839,26.745 4.003,26.745 U2.38@4.568,27.309 U2.38@4.272,27.309 ; C60.1@3.405,22.144 3.405,22.938 3.861,23.393 5.157,23.393 12.142,16.408 24.581,16.408 26.435,18.263 v2(26.467,18.263)
  Top Layer w0.2: U5.5@2.949,20.763 2.949,21.688 C60.1@3.405,22.144
P5V0: C59.1 C64.1 C65.1 C66.1 C67.1 C68.1 L3.2 R46.2 R49.2 U2.34-35 U5.1 | length 34.1
  Top Layer w0.2: U5.1@2.949,18.013 2.949,18.417 4.002,19.471 R46.2@6.086,19.471 ; C59.1@3.107,16.081 2.946,16.242 2.946,17.82 U5.1@3.14,18.013
  Top Layer w0.5: L3.2@13.215,6.7 L3.2@14.002,6.7
  Bottom Layer w0.2: v1(5.249,4.095) 5.249,1.651 5.935,0.965 17.704,0.965 20.371,3.632 27.218,3.632 v2(28.215,4.629)
  other v1: 1.543,3.318 2.255,3.318 3.652,3.318 2.966,3.344 1.543,3.831 2.255,3.831 3.652,3.831 2.966,3.857 5.762,4.095 6.29,4.095 6.803,4.095 7.283,4.095 7.796,4.095 8.287,4.095 8.8,4.095 9.313,4.095 9.826,4.095 10.521,4.095 11.033,4.095 11.546,4.095 12.059,4.095 12.55,4.095 13.063,4.095 13.576,4.095 14.088,4.095 1.543,4.36 2.255,4.36 3.652,4.36 2.966,4.385 5.274,4.781 5.787,4.781 6.316,4.781 6.828,4.781 7.309,4.781 7.822,4.781 8.313,4.781 8.825,4.781 9.338,4.781 9.851,4.781 10.546,4.781 11.059,4.781 11.572,4.781 12.084,4.781 12.575,4.781 13.088,4.781 13.601,4.781 14.114,4.781 1.543,4.873 2.255,4.873 3.652,4.873 2.966,4.898 1.543,5.353 2.255,5.353 3.652,5.353 2.966,5.378 5.249,5.492 5.762,5.492 6.29,5.492 6.803,5.492 7.283,5.492 7.796,5.492 8.287,5.492 8.8,5.492 9.313,5.492 9.826,5.492 10.521,5.492 11.033,5.492 11.546,5.492 12.059,5.492 12.55,5.492 13.063,5.492 13.576,5.492 14.088,5.492 1.543,5.866 2.255,5.866 3.652,5.866 2.966,5.891 5.249,6.204 5.762,6.204 6.29,6.204 6.803,6.204 7.283,6.204 7.796,6.204 8.287,6.204 8.8,6.204 9.313,6.204 9.826,6.204 10.521,6.204 11.033,6.204 11.546,6.204 12.059,6.204 12.55,6.204 13.063,6.204 13.576,6.204 14.088,6.204 1.543,6.357 2.255,6.357 3.652,6.357 2.966,6.382 1.543,6.87 2.255,6.87 3.652,6.87 2.966,6.895 1.543,7.382 2.255,7.382 3.652,7.382 2.966,7.408 1.543,7.895 2.255,7.895 3.652,7.895 2.966,7.921 1.507,9.338 2.218,9.338 3.615,9.338 2.929,9.364 1.507,9.851 2.218,9.851 3.615,9.851 2.929,9.876 1.507,10.38 2.218,10.38 3.615,10.38 2.929,10.405 1.507,10.892 2.218,10.892 3.615,10.892 2.929,10.918 1.507,11.373 2.218,11.373 3.615,11.373 2.929,11.398 1.507,11.886 2.218,11.886 3.615,11.886 2.929,11.911 1.507,12.377 2.218,12.377 3.615,12.377 2.929,12.402 1.507,12.889 2.218,12.889 3.615,12.889 2.929,12.915 1.507,13.402 2.218,13.402 3.615,13.402 2.929,13.428 1.507,13.915 2.218,13.915 3.615,13.915 2.929,13.94 1.503,14.579 2.214,14.579 3.611,14.579 2.926,14.604 1.503,15.091 2.214,15.091 3.611,15.091 2.926,15.117 1.503,15.62 2.214,15.62 3.611,15.62 2.926,15.645 1.503,16.249 2.214,16.249 3.611,16.249 2.926,16.274 1.503,16.762 2.214,16.762 3.611,16.762 2.926,16.787 1.503,17.29 2.214,17.29 2.926,17.316 1.289,24.705 2.686,24.705 2.001,24.731 1.289,25.218 2.686,25.218 2.001,25.243 1.289,25.747 2.686,25.747 2.001,25.772 1.289,26.259 2.686,26.259 2.001,26.285 1.289,26.74 2.686,26.74 2.001,26.765 1.289,27.253 2.686,27.253 2.001,27.278 1.289,27.744 2.686,27.744 2.001,27.769 1.289,28.256 2.686,28.256 2.001,28.282 1.289,28.769 2.686,28.769 2.001,28.795
  other v4: 3.429,28.042 3.188,28.379 3.655,28.379 3.19,28.829 3.651,28.836
PPHV: C5.1 C6.1 C7.1 C8.1 C9.1 C10.1 C11.1 C54.1 C55.1 C56.1 R1.1 R3.2 R5.1 R7.2 U2.20-21-22 | length 38.3
  Top Layer w0.15: v4(22.778,22.996) 22.914,22.86 v4(26.101,22.86)
  Top Layer w0.2: U2.20-21-22@7.144,32.609 8.342,33.807 11.786,33.807 ; C6.1@12.622,33.456 C6.1@12.775,33.304 ; R1.1@16.661,37.727 17.441,37.727 17.747,37.421 v2(17.747,35.763) v2(17.747,35.255) ; R1.1@16.737,37.972 R1.1@17.026,37.972
  Bottom Layer w0.15: 17.729,37.516 17.795,37.45 17.795,37.018
  Bottom Layer w0.2: C55.1@15.873,33.394 C55.1@16.045,33.223 ; R3.2@16.408,41.483 R3.2@16.776,41.851 ; 16.923,32.997 16.923,32.938 17.355,32.505 17.355,31.168 22.758,25.765 v4@22.758,22.965 ; v2(17.747,35.255) v2(17.747,35.763) v2@17.795,35.811 ; v2@17.805,35.23 17.747,35.172 17.747,31.376 21.569,27.555 v2(23.91,27.555)
  other v1: 14.647,34.108 15.159,34.108 12.024,34.133 12.562,34.133 13.075,34.133 13.588,34.133 14.079,34.133 14.647,34.819 15.159,34.819 12.024,34.845 12.562,34.845 13.075,34.845 13.588,34.845 14.079,34.845 14.697,35.505 15.21,35.505 12.075,35.53 12.613,35.53 13.126,35.53 13.638,35.53 14.129,35.53 14.672,36.14 15.185,36.14 12.049,36.165 12.587,36.165 13.1,36.165 13.613,36.165 14.104,36.165 13.074,36.936 13.565,36.936 14.078,36.936 14.591,36.936 15.129,36.936 11.993,36.961 12.506,36.961
PWR_C0: U2.7
PWR_C1: U2.19
PWR_ERR: U2.18
PWR_SRC: U2.6
REGN: C36.1 R9.1 U1.28 | length 19.3
  Top Layer w0.2: U1.28@32.301,25.001 32.301,26.221 32.53,26.45 C36.1@32.53,27.616 ; C36.1@32.334,27.317 C36.1@32.391,27.374
  Bottom Layer w0.2: v2(23.774,19.279) 23.774,24.46 24.79,25.476 32.385,25.476 32.817,25.908 32.817,27.292 v2(32.611,27.498)
USB3: U2.37
USB_N: J2.A7 J2.B7 U2.27 | length 14.5
  Top Layer w0.15: v6(3.801,31.709) U2.27@4.568,31.709 ; v2(6.339,41.84) 6.339,42.321 7.089,43.071 v2(7.089,43.44)
  Top Layer w0.2: v2(6.339,41.84) 6.35,41.829 v2(6.35,39.421)
  Bottom Layer w0.15: v6(3.801,31.709) 4.125,31.709 4.318,31.902 4.318,38.1 5.639,39.421 v2(6.35,39.421)
USB_P: J2.A6 J2.B6 U2.26 | length 14.2
  Top Layer w0.15: v6(3.886,32.515) 3.886,32.287 4.064,32.109 U2.26@4.568,32.109
  Top Layer w0.2: v2(6.839,41.84) 6.839,40.063 v2(6.87,40.032)
  Bottom Layer w0.15: v6(3.886,32.515) 3.886,38.456 5.463,40.032 v2(6.87,40.032) ; v2@6.87,39.918 v2(6.87,40.032) ; v2@6.87,40.057 v2(6.87,40.032)
  Bottom Layer w0.2: v2(6.589,43.44) 6.589,42.712 6.839,42.462 v2(6.839,41.84)
VBUS: C51.1 L2.2 U2.23-24-25 U2.32-33 | length 12.2
  Top Layer w0.15: 3.421,33.063 2.719,32.361 2.719,30.173 3.383,29.509 U2.32-33@4.568,29.509 U2.32-33@4.565,29.506 ; 6.245,33.063 6.263,33.081 ; C51.1@6.591,35.122 6.597,35.128 L2.2@6.597,37.38
  Top Layer w0.2: 3.421,33.063 3.454,33.096 5.304,33.096 U2.23-24-25@5.791,32.609 6.245,33.063 ; 6.263,33.081 6.245,33.099 6.245,33.932 6.629,34.317
  other v1: 1.442,29.798 2.153,29.823 1.442,30.311 2.153,30.336 1.442,30.839 2.153,30.865 1.442,31.352 2.153,31.377 1.442,31.832 2.153,31.858
VDDA: C33.1 R9.2 R11.1 R14.2 U1.7 | length 24.6
  Top Layer w0.15: R9.2@25.17,19.39 26.578,19.39 C33.1@27.736,20.549
  Top Layer w0.2: C33.1@27.685,20.573 27.685,21.164 27.716,21.195 28.615,21.195 29.411,21.99 U1.7@30.101,21.99
  Bottom Layer w0.2: v2(25.146,19.304) 25.146,17.551 26.619,16.078 30.15,16.078 30.935,16.863 30.935,20.115 31.75,20.93 35.255,20.93 36.043,20.142 v2(36.703,20.142)
pads on no net: CN1.2 J2.A2 J2.A3 J2.A8 J2.A10 J2.A11 J2.ALIGN1 J2.ALIGN2 J2.B2 J2.B3 J2.B8 J2.B10 J2.B11 Q1.9A Q1.9B Q1.9C Q1.9D Q2.9A Q2.9B Q2.9C Q2.9D Q3.9A Q3.9B Q3.9C Q3.9D Q4.9A Q4.9B Q4.9C Q4.9D U1.4 U1.11 U1.15 U1.21 U3.7@8.065,47.524 U3.7@8.065,48.424 U5.4

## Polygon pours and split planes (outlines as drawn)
no net on Top Layer "Top Layer-No Net 1" (solid, pour order 114): 19.431,12.929
GND on Top Layer "Top Layer-GND 9" (solid, pour order 106): 4.648,32.361 4.648,27.129 3.313,25.794 3.313,17.564 11.125,17.564 11.125,32.361
GND on Top Layer "Top Layer-GND 10" (solid, remove dead copper, pour order 104): 8.674,27.127 22.174,27.127 22.174,13.904 22.088,13.818 8.674,13.818
VBUS on Top Layer "Top Layer-VBUS" (solid, pour order 94): 0.965,33.62 0.965,29.362 1.219,29.108 4.757,29.108 5.055,29.406 5.055,29.769 4.851,29.972 4.013,29.972 4.013,32.308 4.064,32.359 4.216,32.207 6.452,32.207 6.452,33.62
GND on Top Layer "Top Layer-GND 6" (solid, pour order 82): 25.121,10.744 40.208,10.744 41.704,12.24 41.704,16.408 47.015,16.408 47.015,8.687 45.999,7.671 45.999,3.632 44.653,2.286 29.641,2.286 25.121,6.806
GND on Top Layer "Top Layer-GND 7" (solid, pour order 78): 4.597,12.802 7.798,12.802 7.798,17.043 7.798,17.145 7.747,17.145 4.597,17.145
P5V0 on Top Layer "Top Layer-P5V0 2" (solid, pour order 76): 0.991,8.534 0.991,29.083 3.962,29.083 4.064,28.981 4.064,8.534
GND on Top Layer "Bottom Layer-GND" (solid, pour order 72): 22.566,26.772 22.566,16.053 41.377,16.053 41.377,27.914 41.3,27.991 23.516,27.991 22.566,27.042
GND on Top Layer "Top Layer-GND 8" (solid, pour order 64): 0.94,49.378 0.94,33.734 5.512,33.734 5.512,36.093 3.508,36.093 3.277,36.325 3.277,40.872 4.086,41.681 7.747,41.681 8.23,41.199 12.471,41.199 15.723,44.45 15.723,49.378
PPHV on Top Layer "Top Layer-PPHV 1" (solid, pour order 62): 6.514,33.02 6.511,32.319 6.597,32.233 8.077,32.233 8.639,32.794 8.639,35.027 8.521,35.027
VBUS on Top Layer "Top Layer-VBUS 1" (solid, pour order 60): 5.766,34.468 4.816,33.518 4.816,32.505 5.089,32.233 6.447,32.233 6.447,33.081 8.368,35.001 8.368,38.531 6.223,38.531 5.766,38.075
NetC45_1 on Top Layer "Top Layer-NetC45_1" (solid, pour order 58): 3.505,36.322 5.639,36.322 5.639,38.077 6.15,38.589 9.119,38.589 9.119,42.24 3.505,42.24
GND on Top Layer "Top Layer-GND" (solid, pour order 46): 9.195,37.592 15.748,37.592 15.748,39.395 15.748,49.149 9.195,49.149
P5V0 on Top Layer "Top Layer-P5V0" (solid, pour order 42): 2.718,29.058 4.877,29.058 4.877,28.397 4.318,28.397 4.242,28.321 4.039,28.118 4.039,27.686 3.81,27.457 3.122,27.457 2.718,27.862
BAT on Top Layer "Top Layer-BAT" (solid, pour order 36): 47.572,17.247 47.572,8.151 46.609,7.188 46.634,7.163 46.634,1.397 47.092,1.397 50.978,1.397 50.978,21.898 47.547,21.898
GND on Top Layer "Top Layer-GND 1" (solid, pour order 34): 22.399,28.346 42.012,28.346 42.012,30.088 42.012,30.988 22.399,30.988
GND on Top Layer "Top Layer-GND 2" (solid, pour order 26): 22.602,6.744 29.5,6.744 34.275,6.744 34.656,6.364 34.656,3.848 33.03,2.223 22.602,2.223
P5V0 on Top Layer "Top Layer-P5V0 1" (solid, pour order 24): 1.067,8.58 1.067,0.559 17.018,0.559 17.018,8.58
BAT on Top Layer "Top Layer-BAT 1" (solid, pour order 22): 18.593,5.353 21.47,8.23 22.921,8.23 22.921,6.817 22.327,6.223 22.327,1.918 34.644,1.918 51.029,1.918 51.029,0.369 18.681,0.369 18.593,0.457
GND on Top Layer "Top Layer-GND 3" (solid, pour order 20): 4.597,8.915 23.11,8.915 23.11,6.813 22.602,6.305 22.602,2.775 25.396,2.775 25.396,3.359 25.396,7.847 25.396,13.138 12.874,13.138 4.597,13.138
NetC1_1 on Top Layer "Top Layer-NetC1_1" (solid, pour order 16): 41.628,37.467 42.015,37.081 43.795,37.081 44.407,37.694 49.274,37.694 49.274,36.525 48.689,35.941 47.8,35.941 47.445,35.585 47.445,23.452 50.899,23.452 50.899,49.327 41.628,49.327
GND on Top Layer "Top Layer-GND 4" (solid, pour order 14): 43.417,36.155 43.417,32.419 41.704,30.706 41.704,16.18 47.038,16.18 47.038,27.657 47.038,35.687 47.597,36.246 48.41,36.246 48.918,36.754 48.918,37.561 44.823,37.561
NetC3_1 on Top Layer "Top Layer-NetC3_1" (solid, pour order 12): 15.946,49.345 15.946,34.512 24.659,34.512 24.659,49.345
PPHV on Top Layer "Top Layer-PPHV" (solid, pour order 10): 8.56,32.632 17.447,32.632 17.447,38.636 8.56,38.636
GND on Top Layer "Top Layer-GND 5" (solid, pour order 8): 10.571,32.321 18.091,32.321 18.487,32.717 18.487,34.474 21.19,34.48 21.869,35.16 22.536,35.16 22.536,27.407 10.571,27.407
no net on Top Layer "Top Layer-No Net" (solid, pour order 4): 16.127,37.795
NetC23_2 on Top Layer "Top Layer-NetC23_2" (solid, pour order 2): 32.791,49.327 41.159,49.327 41.159,37.317 42.954,35.817 42.954,32.616 41.812,31.394 32.791,31.394
NetC22_2 on Top Layer "Top Layer-NetC22_2" (solid, pour order 0): 24.938,36.901 23.735,35.698 23.188,35.698 22.855,35.366 22.855,31.854 23.289,31.42 31.75,31.42 31.75,49.327 24.938,49.327
GND on Bottom Layer "Bottom Layer-GND 13" (solid, pour order 112): 10.881,32.233 10.881,27.292 21.019,27.292 21.019,32.233
GND on Bottom Layer "Bottom Layer-GND 12" (solid, pour order 110): 20.269,3.318 30.378,3.318 30.378,9.322 20.269,9.322
GND on Bottom Layer "Bottom Layer-GND 9" (solid, pour order 102): 37.426,30.988 37.426,28.104 37.414,28.092 41.819,28.092 41.844,28.067 41.895,28.118 41.895,30.963 37.449,30.963 37.44,30.972
GND on Bottom Layer "Bottom Layer-GND 10" (solid, pour order 100): 18.618,33.807 18.618,28.321 22.491,28.321 22.491,34.267 22.291,34.468 19.279,34.468
GND on Bottom Layer "Bottom Layer-GND 11" (solid, pour order 98): 8.313,26.611 8.313,13.437 21.488,13.437 21.488,26.61
VBUS on Bottom Layer "Bottom Layer-VBUS" (solid, pour order 96): 1.092,29.267 0.965,29.394 0.965,32.722 1.041,32.798 2.679,32.798 2.819,32.658 2.819,31.286 3.418,30.688 3.418,29.267 3.286,29.267
NetU2_15 on Bottom Layer "Bottom Layer-NetU2_15" (solid, pour order 92): 5.179,30.404 7.874,30.404 7.874,32.029 7.823,32.08 5.179,32.08
NetC23_2 on Bottom Layer "Top Layer-NetC23_2" (solid, pour order 90): 32.719,49.352 41.086,49.352 41.086,36.817 43.131,36.817 43.131,32.418 42.133,31.42 32.719,31.42
NetC22_2 on Bottom Layer "Top Layer-NetC22_2" (solid, pour order 88): 24.938,36.817 23.735,35.614 23.008,35.614 22.855,35.462 22.855,31.61 23.13,31.336 31.75,31.336 31.75,49.243 24.938,49.243
NetC3_1 on Bottom Layer "Bottom Layer-NetC3_1" (solid, pour order 86): 16.096,49.352 16.096,39.911 16.815,39.192 18.923,39.192 18.923,34.97 22.355,34.975 24.697,37.317 24.697,49.293 24.638,49.352
GND on Bottom Layer "Bottom Layer-GND 6" (solid, pour order 84): 30.16,3.15 44.933,3.15 46.997,5.214 46.997,11.735 30.16,11.735
BAT on Bottom Layer "Bottom Layer-BAT" (solid, pour order 80): 47.422,21.719 47.422,4.674 45.707,2.959 22.708,2.959 22.466,3.2 20.701,3.2 20.701,0.623 20.955,0.369 50.356,0.369 51.384,1.397 51.384,22.047 47.75,22.047
PPHV on Bottom Layer "Bottom Layer-PPHV 1" (solid, pour order 74): 15.824,36.678 15.799,36.652 15.818,36.633 17.856,36.633 17.856,37.744 17.856,42.327 17.638,42.545 15.824,42.545
NetC1_1 on Bottom Layer "Top Layer-NetC1_1" (solid, pour order 68): 41.427,37.135 43.849,37.135 44.458,37.744 48.539,37.744 48.539,35.791 47.496,34.747 47.496,22.572 51.333,22.572 51.333,49.276 41.427,49.276
GND on Bottom Layer "Bottom Layer-GND 7" (solid, pour order 66): 43.358,34.646 43.358,32.156 41.783,30.582 41.783,8.88 47.168,8.88 47.168,34.722 48.336,35.89 48.336,37.541 44.448,37.541 43.358,36.451
GND on Bottom Layer "Bottom Layer-GND 8" (solid, pour order 56): 0.94,32.537 15.433,32.537 15.433,49.301 0.94,49.301
GND on Bottom Layer "Bottom Layer-GND" (solid, pour order 54): 22.327,27.102 22.327,19.091 25.035,16.383 39.638,16.383 41.137,17.882 41.137,27.087 40.615,27.61 22.835,27.61
GND on Bottom Layer "Bottom Layer-GND 1" (solid, pour order 52): 30.086,24.46 30.086,21.628 30.48,21.234 30.632,21.234 34.15,21.234 36.271,23.355 36.271,30.963 30.632,30.963 30.632,27.947 32.741,27.947 32.741,24.74 32.453,24.452 30.099,24.452
GND on Bottom Layer "Bottom Layer-GND 2" (solid, pour order 50): 30.516,30.988 30.516,27.815 20.061,27.815 20.061,30.988
PPHV on Bottom Layer "Bottom Layer-PPHV" (solid, pour order 48): 11.608,32.588 17.272,32.588 17.272,38.964 11.608,38.964
GND on Bottom Layer "Bottom Layer-GND 3" (solid, pour order 44): 6.426,30.023 8.687,30.023 8.687,42.672 10.033,44.018 15.406,44.018 15.406,39.192 11.443,39.192 11.361,27.498 9.565,27.498 6.426,27.498
P5V0 on Bottom Layer "Bottom Layer-P5V0" (solid, pour order 40): 0.991,29.159 0.991,2.438 4.223,2.438 4.223,29.159
GND on Bottom Layer "Bottom Layer-GND 4" (solid, pour order 38): 5.09,30.048 5.09,13.03 7.932,13.03 7.932,30.048
P5V0 on Bottom Layer "Bottom Layer-P5V0 1" (solid, pour order 32): 0.948,0.737 16.942,0.737 16.942,9.068 0.948,9.068
GND on Bottom Layer "Bottom Layer-GND 5" (solid, pour order 28): 5.08,13.189 5.08,9.195 34.747,9.195 34.747,13.189
no net on Top Solder (solid): 18.212,28.702 42.704,28.702 42.704,30.616 18.212,30.616
no net on Top Solder (solid): 5.004,9.83 5.004,8.992 20.574,8.992 20.599,8.992 20.599,9.804 20.599,9.83 20.422,9.83
no net on Top Solder (solid): 24.384,13.081 25.324,13.081 25.324,10.598 24.409,10.598 24.384,10.598
GND on Top Solder (solid): 5.005,13.081 24.409,13.081 24.409,9.754 5.005,9.754
no net on Top Solder (solid): 1.346,8.382 16.882,8.382 16.882,0.991 1.346,0.991
NetC1_1 on Top Solder (solid): 42.045,49.073 42.045,37.846 50.388,37.846 50.388,49.073
NetC23_2 on Top Solder (solid): 33.299,49.149 33.299,32.055 40.31,32.055 40.31,49.149
NetC22_2 on Top Solder (solid): 25.806,49.124 25.806,32.084 31.4,32.084 31.4,49.098 31.375,49.124
no net on Top Solder (solid): 16.637,49.174 16.637,39.552 24.308,39.552 24.308,49.149 24.282,49.174

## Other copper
Top Layer:
  pour cut-out: 17.348,34.557 18.82,34.557 18.82,38.817 17.348,38.817
  pour cut-out: 16.002,38.862 20.089,38.862 20.165,38.786 20.165,35.916 20.241,35.839 20.419,35.839 20.419,38.989 20.284,39.124 16.002,39.124
Bottom Layer:
  pour cut-out: 5.08,27.33 5.918,27.33 5.918,24.79 5.893,24.765 5.09,24.765 5.08,24.775

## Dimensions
0,50.013 to 0,-0.025 on Top Overlay
-0.025,49.962 to 51.841,50.013 on Top Overlay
